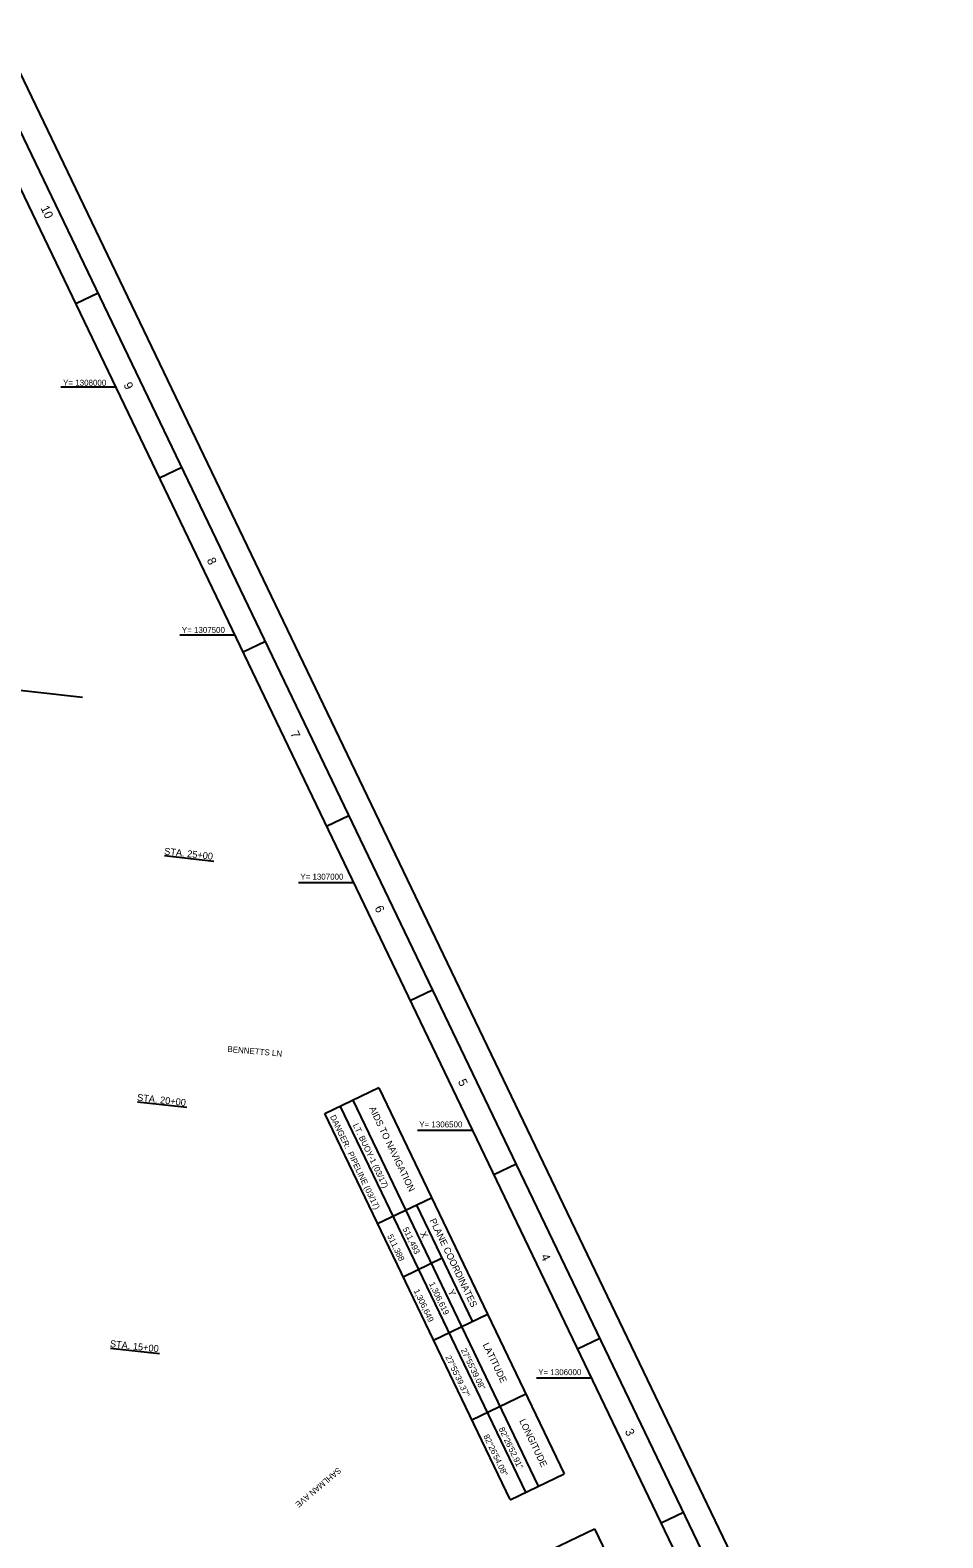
# Model space of a CAD drawing. Extents: x 508947 to 513916, y 1303283 to 1308721.
# Drawn here: x 512074 to 513916, y 1305678 to 1308721 of the extents above; entities that cross this region are included whole.
import ezdxf

# ---------------------------------------------------------------- set-up
doc = ezdxf.new("R2010")
doc.units = 0
for name, color, linetype in [('G-ANNO-NPLT', 7, 'Continuous'), ('G-ANNO-TTLB', 7, 'Continuous'), ('V-ALGN-TEXT', 7, 'Continuous'), ('V-ANNO-MATC', 7, 'Continuous'), ('V-ANNO-SCHD', 7, 'Continuous'), ('V-ANNO-SYMB', 7, 'Continuous'), ('V-ROAD-IDEN', 7, 'Continuous'), ('V-TOPO-COOR-STAT', 7, 'Continuous')]:
    doc.layers.add(name, color=color, linetype=linetype)

msp = doc.modelspace()

# ---------------------------------------------------------------- linework, layer by layer
at = {"layer": 'G-ANNO-NPLT'}
msp.add_lwpolyline([(512011.7, 1308720.8), (513916.1, 1304754.3), (510851.1, 1303282.7), (508946.7, 1307249.2)], close=True, dxfattribs=at)
at = {"layer": 'G-ANNO-TTLB'}
for p, q in [((512211.2, 1308189.8), (512166.1, 1308168.2)), ((512380, 1307838.3), (512334.9, 1307816.6)), ((512380, 1307838.3), (512334.9, 1307816.6)), ((512548.8, 1307486.7), (512503.7, 1307465.1)), ((512717.6, 1307135.1), (512672.5, 1307113.5)), ((512886.4, 1306783.5), (512841.3, 1306761.9)), ((513055.2, 1306432), (513010.1, 1306410.3)), ((513224, 1306080.4), (513178.9, 1306058.7)), ((513392.8, 1305728.8), (513347.7, 1305707.2))]:
    msp.add_line(p, q, dxfattribs=at)
for points in [[(509013.4, 1307225.8), (510874.5, 1303349.5), (513849.4, 1304777.8), (511988.3, 1308654.1)], [(513782.7, 1304801.2), (511997.3, 1308519.8), (509112.6, 1307134.8), (510898, 1303416.2)]]:
    msp.add_lwpolyline(points, close=True, dxfattribs=at)
at = {"layer": 'V-ALGN-TEXT'}
for p, q in [((512444.9, 1307043.2), (512345.5, 1307054.1)), ((512390.1, 1306546.2), (512290.8, 1306557.1)), ((512335.4, 1306049.2), (512236, 1306060.1))]:
    msp.add_line(p, q, dxfattribs=at)
at = {"layer": 'V-ANNO-MATC'}
msp.add_line((512179.6, 1307374.2), (511384.4, 1307461.8), dxfattribs=at)
at = {"layer": 'V-ANNO-SCHD'}
for p, q in [((512777.6, 1306586.1), (512668.6, 1306533.8)), ((512777.6, 1306586.1), (513151.6, 1305807.2)), ((512699.5, 1306548.6), (513073.5, 1305769.7)), ((512725.6, 1306561.1), (513099.5, 1305782.2)), ((512668.4, 1306534.2), (513042.4, 1305755.3)), ((512884.4, 1306363.7), (512775.4, 1306311.4)), ((512854, 1306349.1), (512966.8, 1306114.1)), ((512905.5, 1306242), (512826.8, 1306204.2)), ((512997.2, 1306128.7), (512888.2, 1306076.4)), ((513074.4, 1305967.9), (512965.4, 1305915.6)), ((513042.6, 1305754.8), (513151.6, 1305807.2))]:
    msp.add_line(p, q, dxfattribs=at)
at = {"layer": 'V-ANNO-SYMB'}
msp.add_lwpolyline([(513213.1, 1305695.9), (513480.2, 1305139.4), (512855.9, 1304839.6), (512588.8, 1305396.1)], close=True, dxfattribs=at)
at = {"layer": 'V-TOPO-COOR-STAT'}
for p, q in [((512246.8, 1308000), (512135.9, 1308000)), ((512486.9, 1307500), (512376, 1307500)), ((512727, 1307000), (512616, 1307000)), ((512967, 1306500), (512856.1, 1306500)), ((513207.1, 1306000), (513096.2, 1306000))]:
    msp.add_line(p, q, dxfattribs=at)

# ---------------------------------------------------------------- texts
at = {"layer": 'G-ANNO-TTLB'}
for s, p in [('10', (512094.7, 1308361.8)), ('9', (512262, 1308005.3)), ('8', (512430.1, 1307651.4)), ('7', (512598.9, 1307301.3)), ('6', (512768.8, 1306949.2)), ('5', (512936.9, 1306599)), ('4', (513104.2, 1306246.2)), ('3', (513273.8, 1305893.1))]:
    msp.add_text(s, height=17.5, rotation=295.6468, dxfattribs=at).set_placement(p)
at = {"layer": 'V-ALGN-TEXT'}
for s, p in [('STA. 25+00', (512344.1, 1307057.1)), ('STA. 20+00', (512289.4, 1306560.1)), ('STA. 15+00', (512234.6, 1306063.1))]:
    msp.add_text(s, height=13.92, rotation=353.7132, dxfattribs=at).set_placement(p)
at = {"layer": 'V-ANNO-SCHD'}
for s, height, p in [('AIDS TO NAVIGATION', 13.471, (512758, 1306544.6)), ('PLANE COORDINATES', 13.471, (512879.9, 1306318.6)), ('X', 13.5, (512860.5, 1306292.2)), ('Y', 13.5, (512916.7, 1306175.3)), ('LATITUDE', 13.47, (512987.1, 1306067.6)), ('LONGITUDE', 13.47, (513060.8, 1305914))]:
    msp.add_text(s, height=height, rotation=295.6468, dxfattribs=at).set_placement(p)
at = {"layer": 'V-ANNO-SYMB'}
for s, p in [('DANGER:  PIPELINE (03/17)', (512678.9, 1306528)), ('LT. BUOY-1 (03/17)', (512725.1, 1306510.9)), ('511,493', (512825.6, 1306301.5)), ('511,388', (512794.5, 1306287.1)), ('1,306,649', (512847.7, 1306176.4)), ('1,306,619', (512878.8, 1306190.8)), ('27%%D55\'39.08"', (512943, 1306057)), ('27%%D55\'39.37"', (512911.9, 1306042.6)), ('82%%D26\'54.08"', (512988.4, 1305883.2)), ('82%%D26\'52.91"', (513019.5, 1305897.6))]:
    msp.add_text(s, height=12, rotation=295.6468, dxfattribs=at).set_placement(p)
at = {"layer": 'V-ROAD-IDEN'}
for s, rotation, p in [('BENNETTS LN', 355.0664, (512471.9, 1306658.6)), ('SAHLMAN AVE', 220.0702, (512695.5, 1305820.7))]:
    msp.add_text(s, height=12, rotation=rotation, dxfattribs=at).set_placement(p)
at = {"layer": 'V-TOPO-COOR-STAT'}
for s, p in [('Y= 1308000', (512140.7, 1308003.2)), ('Y= 1307500', (512380.2, 1307504.2)), ('Y= 1307000', (512619.4, 1307006.2)), ('Y= 1306500', (512859.4, 1306506.2)), ('Y= 1306000', (513099.5, 1306006.2))]:
    msp.add_text(s, height=12, rotation=360, dxfattribs=at).set_placement(p)

doc.saveas('drawing.dxf')
